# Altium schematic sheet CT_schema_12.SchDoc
size 274 x 160 mm
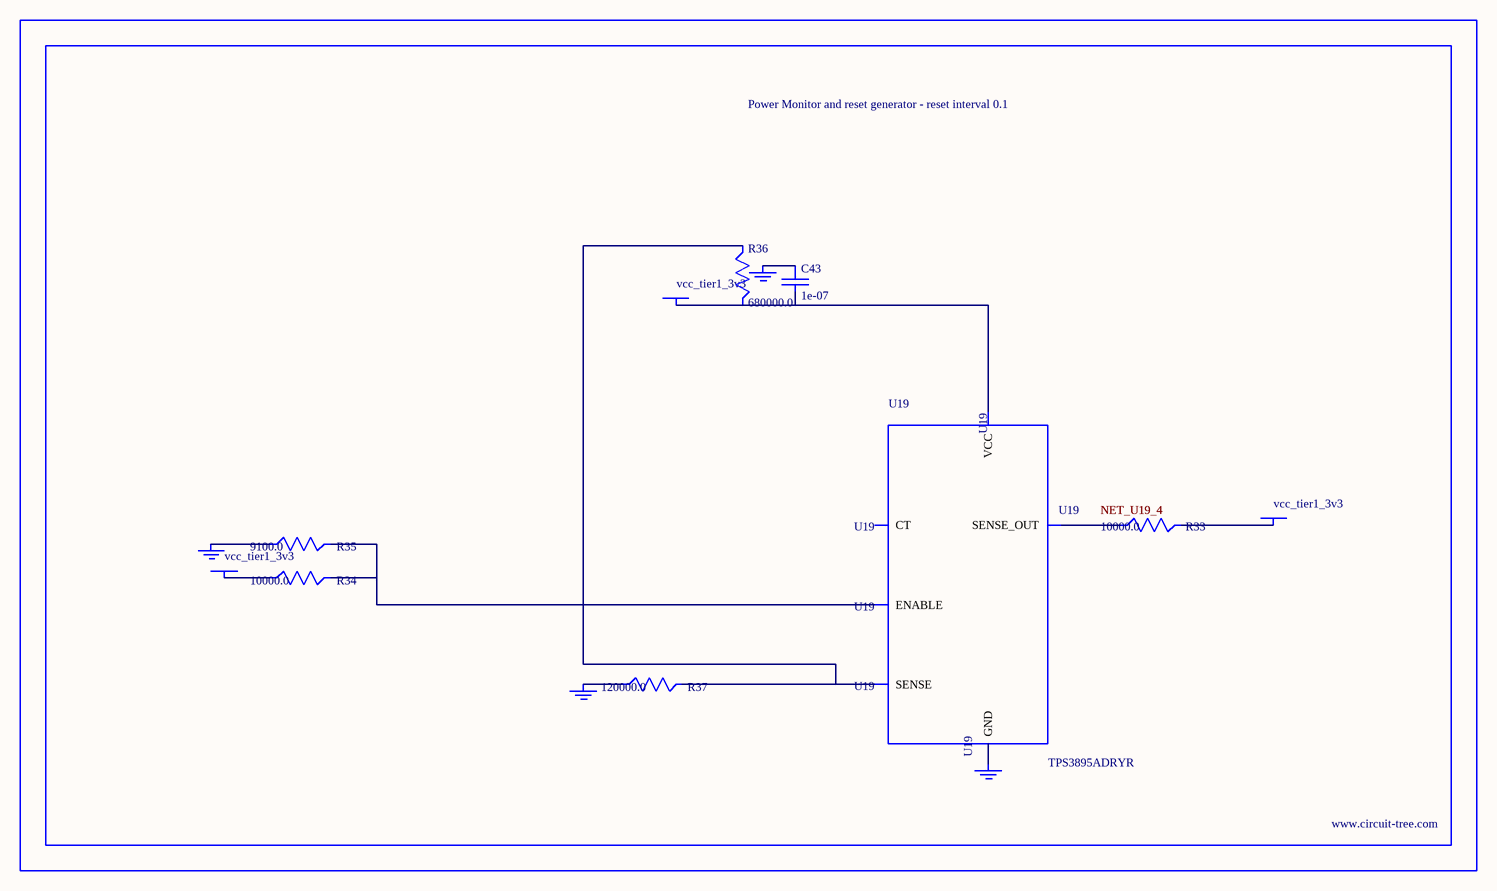
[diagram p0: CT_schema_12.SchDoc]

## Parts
BORDER11  (no value)
C43  1e-07  [C0402]
GND_INSTANCE_11_0  (no value)
GND_INSTANCE_11_1  (no value)
GND_INSTANCE_11_2  (no value)
GND_INSTANCE_11_3  (no value)
POWER_INSTANCE_11_0  vcc_tier1_3v3
POWER_INSTANCE_11_1  vcc_tier1_3v3
POWER_INSTANCE_11_2  vcc_tier1_3v3
R33  10000.0  [R0603]
R34  10000.0  [R0603]
R35  9100.0  [R0603]
R36  680000.0  [R0603]
R37  120000.0  [R0603]
U19  TPS3895ADRYR  [SON-6]

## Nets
NetC43_1: C43.1 GND_INSTANCE_11_2.0(GND)
NetC43_2: C43.2 POWER_INSTANCE_11_2.0(PWR) R36.2 U19.6(VCC)
NetGND_INSTANCE_11_0_0: GND_INSTANCE_11_0.0(GND) R35.1
NetGND_INSTANCE_11_1_0: GND_INSTANCE_11_1.0(GND) R37.1
NetGND_INSTANCE_11_3_0: GND_INSTANCE_11_3.0(GND) U19.2(GND)
NetPOWER_INSTANCE_11_0_0: POWER_INSTANCE_11_0.0(PWR) R34.1
NetPOWER_INSTANCE_11_1_0: POWER_INSTANCE_11_1.0(PWR) R33.2
NetR33_1: R33.1 U19.4(SENSE_OUT)
NetR34_2: R34.2 R35.2 U19.1(ENABLE)
NetR36_1: R36.1 R37.2 U19.3(SENSE)

Not connected (* = marked no-connect by the designer): U19 5(CT)

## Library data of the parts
BORDER11 = BORDER_PAGE11
C43 = C0402C104K3RACTU
GND_INSTANCE_11_0-GND_INSTANCE_11_3 = GND
POWER_INSTANCE_11_0-POWER_INSTANCE_11_2 = PWR
R33 R34 = RC0603JR-0710KL
R35 = RC0603JR-079K1L
R36 = RC0603JR-07680KL
R37 = RC0603JR-07120KL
